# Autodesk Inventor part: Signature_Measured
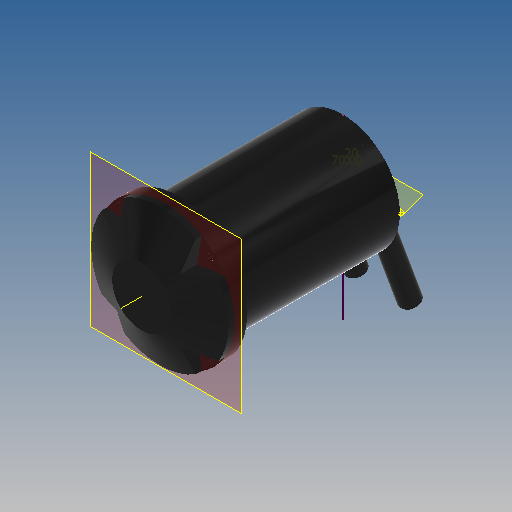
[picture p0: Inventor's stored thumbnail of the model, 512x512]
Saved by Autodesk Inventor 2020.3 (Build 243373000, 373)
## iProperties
Created: 2020-09
Part Number: Signature_Measured
Material: Acetal Resin, Black
Document SubType Name: Modeling
Designer: biggshj
Manufacturer: Standard
Standards Organization: Custom
Density: 0.941369 g/cm^3
Appearance: Smooth - Black
Mass: 2238.6 g
Surface Area: 1209.11 cm^2
Volume: 2378.03 cm^3
Company: NIWA Instrument Systems
Author: biggshj
Revision Number: 1
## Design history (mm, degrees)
sketch "Sketch1"
  geometry: C1 r 59 at (0, 0); 1 further point
  constraints: 1 centre point, 1 coincident
  dimensions: "d0" = 118 diameter of C1
extrude "Extrusion1" new body sketch "Sketch1" distance "d1" = 170; taper "d2" = 0 deg
sketch "Sketch2"
  geometry: C1 r 71 at (0, 0); 1 further point
  constraints: 1 centre point, 1 coincident
  dimensions: "d3" = 142 diameter of C1
extrude "Extrusion2" join sketch "Sketch2" distance "d4" = 13; taper "d5" = 0 deg
sketch "Sketch3"
  geometry: L1 (71, 183)-(-71, 183) reference; L2 (0, 183)-(71, 183); L3 (71, 183)-(71, 189); L4 (71, 189)-(30.254, 208); L5 (30.254, 208)-(0, 208); L6 (0, 208)-(0, 183); L7 (0, -65.6)-(0, 253.6) reference; 1 further point
  constraints: 10 end point, 2 perpendicular, 1 collinear, 1 midpoint, 1 parallel
  dimensions: "d6" = 6 distance of L1.start L3.end; "d7" = 115 deg angle of L3 L4; "d8" = 25 distance of L5.end L2.start
workaxis "Work Axis1"
revolve "Revolution1" stored, may be unused: angle "d9" = 360 deg
sketch "Sketch4"
  geometry: L1 (0, 0)-(-71.954, 0); L2 (0, 0)-(-45.962, 45.962); C1 r 3.25 at (-45.962, 45.962)
  constraints: 4 end point, 1 centre point, 1 horizontal
  dimensions: "d10" = 6.5 diameter of C1; "d11" = 65 distance of L1.start L2.end; "d33" = 45 deg angle of L1 L2
extrude "Extrusion3" cut sketch "Sketch4" distance "d12" = 50; taper "d13" = 0 deg
workplane "Work Plane1"
sketch "Sketch5"
  geometry: L1 (-50.205, 50.205)-(-62.933, 37.477); L2 (-62.933, 37.477)-(-32.527, 32.527); L3 (-32.527, 32.527)-(-37.477, 62.933); L4 (-37.477, 62.933)-(-50.205, 50.205); L5 (-45.962, 45.962)-(0, 0); L6 (0, 0)-(-71, 0); C1 r 3.25 at (-45.962, 45.962) reference; 1 further point
  constraints: 12 end point, 3 point on line, 1 collinear, 1 equal length, 1 horizontal, 1 horizontal alignment, 3 other
  dimensions: "d15" = 18 distance of L1.start L1.end; "d16" = 18 distance of L3.end L1.start; "d17" = 25 distance of L1.start L2.end
extrude "Extrusion4" cut sketch "Sketch5" distance "d18" = 50; taper "d19" = 0 deg
pattern_circular "Circular Pattern1" dims angle "d21" = 360 deg
sketch "Sketch6"
  geometry: L1 (0, 0)-(-123.821, 0); L2 (59, 0)-(-59, 0) reference; L3 (0, 0)-(7.279, 0); L4 (7.279, -20)-(0, 0); L5 (7.279, -20)-(7.279, 0)
  constraints: 8 end point, 1 collinear, 1 perpendicular, 1 point on line
  dimensions: "d23" = 70 deg angle of L2 L4; "d24" = 20 distance of L4.start L3.end
workplane "Work Plane2"
  workpoint "Work Point1"
  workpoint "Work Point2"
  workpoint "Work Point3"
sketch "Sketch7"
  geometry: L1 (21.284, 0)-(21.284, 28); L2 (21.284, 0)-(21.284, -28); C1 r 10 at (21.284, 28); C2 r 10 at (21.284, -28)
  constraints: 4 end point, 2 centre point, 2 coincident, 2 vertical
  dimensions: "d25" = 20 diameter of C2; "d26" = 20 diameter of C1; "d27" = 28 distance of L1.start L1.end; "d28" = 28 distance of L1.start L2.end
extrude "Extrusion5" join sketch "Sketch7" distance "d29" = 30; taper "d31" = 0 deg; dims "d30" = 120, "d32" = 0
body "Solid1"
other parameters: "d14" = -13
